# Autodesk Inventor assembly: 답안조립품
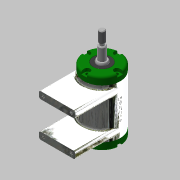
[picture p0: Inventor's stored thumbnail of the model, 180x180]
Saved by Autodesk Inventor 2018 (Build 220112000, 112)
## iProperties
Created: 2020-07
Part Number: 답안조립품
Material: 일반
Document SubType Name: Assembly
Designer: home
Author: home
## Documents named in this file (8)
- C:\Users\home\Desktop\700706V1027\답안조립품.iam
- C:\Users\home\Desktop\700706V1027\본체.ipt
- C:\Users\home\Desktop\700706V1027\베어링 6002.ipt
- C:\Users\home\Desktop\700706V1027\축.ipt
- C:\Users\home\Desktop\700706V1027\앞커버.ipt
- C:\Users\home\Desktop\700706V1027\뒤커버.ipt
- C:\Users\home\Desktop\700706V1027\오일 실 15 25 7.ipt
- C:\Users\home\Desktop\700706V1027\키 3x3x12.ipt
